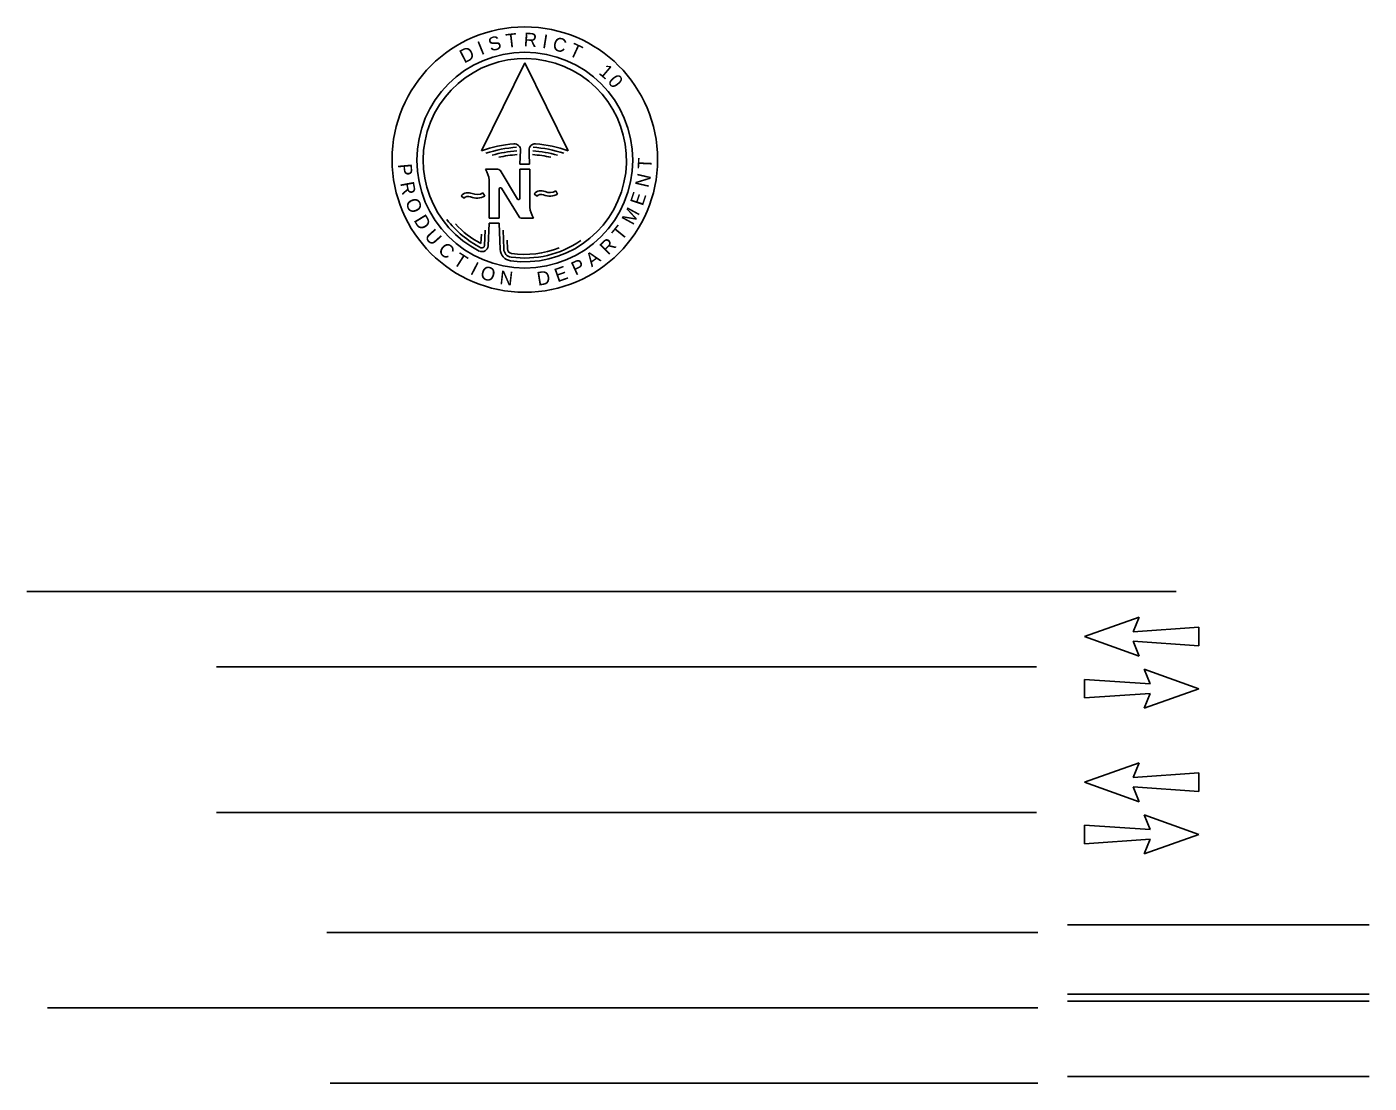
# Model space of a CAD drawing. Extents: x 396.2 to 468.4, y 232.6 to 279.1.
# Drawn here: x 423.05 to 428.91, y 248.41 to 253.02 of the extents above; entities that cross this region are included whole.
import ezdxf

# ---------------------------------------------------------------- set-up
doc = ezdxf.new("R2010")
doc.units = 0
doc.layers.add('Default', color=7, linetype='Continuous')

msp = doc.modelspace()

# ---------------------------------------------------------------- linework, layer by layer
at = {"layer": 'Default'}
for p, q in [((425.0306, 252.4821), (425.2196, 252.8661)), ((425.2196, 252.8661), (425.4086, 252.4821)), ((425.1983, 252.4232), (425.2006, 252.485)), ((425.2403, 252.4232), (425.1983, 252.4232)), ((425.2195, 252.4413), (425.2195, 252.4413)), ((425.2195, 252.4413), (425.2195, 252.4413)), ((425.2196, 252.4413), (425.2196, 252.4413)), ((425.2196, 252.4413), (425.2196, 252.4413)), ((425.2196, 252.4413), (425.2196, 252.4413)), ((425.2196, 252.4413), (425.2196, 252.4413)), ((425.0484, 252.4019), (425.1021, 252.4019)), ((425.1113, 252.3968), (425.1876, 252.271)), ((425.1975, 252.2738), (425.1975, 252.4019)), ((425.1975, 252.4019), (425.2412, 252.4019)), ((425.2412, 252.4019), (425.2412, 252.236)), ((425.0644, 252.1879), (425.0644, 252.3537)), ((425.1081, 252.3159), (425.1081, 252.1879)), ((425.1943, 252.1931), (425.1181, 252.3187)), ((425.363, 252.2929), (425.3553, 252.3068)), ((424.9416, 252.2859), (424.9533, 252.2748)), ((425.0447, 252.2843), (425.037, 252.2983)), ((425.26, 252.2946), (425.2717, 252.2835)), ((425.1081, 252.1879), (425.0644, 252.1879)), ((425.2573, 252.1879), (425.2035, 252.1879)), ((425.0469, 252.136), (425.0437, 252.0678)), ((425.0644, 252.1665), (425.0596, 252.0666)), ((425.1081, 252.1665), (425.0644, 252.1665)), ((425.1114, 252.0513), (425.1081, 252.1665)), ((425.1251, 252.1351), (425.1274, 252.0537)), ((425.0301, 252.1181), (425.0282, 252.0768)), ((425.1424, 252.0917), (425.1435, 252.0542)), ((428.0631, 250.5579), (423.0455, 250.5579)), ((427.6636, 250.3607), (427.9015, 250.4459)), ((427.9015, 250.4459), (427.8762, 250.3811)), ((427.8762, 250.3811), (428.1621, 250.4013)), ((428.1621, 250.4013), (428.162, 250.3197)), ((427.9015, 250.2753), (427.6636, 250.3607)), ((428.162, 250.3197), (427.8763, 250.3402)), ((427.8763, 250.3402), (427.9015, 250.2753)), ((427.4541, 250.2291), (423.8741, 250.2291)), ((427.9495, 250.1536), (427.924, 250.2184)), ((427.924, 250.2184), (428.1623, 250.133)), ((427.6637, 250.0924), (427.6635, 250.1736)), ((427.6635, 250.1736), (427.9495, 250.1536)), ((428.1623, 250.133), (427.9244, 250.0478)), ((427.9495, 250.1125), (427.6637, 250.0924)), ((427.9244, 250.0478), (427.9495, 250.1125)), ((427.6636, 249.7244), (427.9015, 249.8096)), ((427.9015, 249.8096), (427.8762, 249.7448)), ((427.9015, 249.639), (427.6636, 249.7244)), ((427.8762, 249.7448), (428.1621, 249.765)), ((428.1621, 249.765), (428.162, 249.6835)), ((428.162, 249.6835), (427.8763, 249.7039)), ((427.8763, 249.7039), (427.9015, 249.639)), ((427.4541, 249.5928), (423.8741, 249.5928)), ((427.9495, 249.5174), (427.924, 249.5822)), ((427.924, 249.5822), (428.1623, 249.4967)), ((427.6637, 249.4561), (427.6635, 249.5373)), ((427.6635, 249.5373), (427.9495, 249.5174)), ((428.1623, 249.4967), (427.9244, 249.4115)), ((427.9495, 249.4762), (427.6637, 249.4561)), ((427.9244, 249.4115), (427.9495, 249.4762)), ((428.9061, 249.1024), (427.5888, 249.1024)), ((427.4593, 249.0677), (424.3551, 249.0677)), ((428.9061, 248.7987), (427.5888, 248.7987)), ((427.4593, 248.739), (423.1359, 248.739)), ((428.9061, 248.7687), (427.5888, 248.7687)), ((428.9061, 248.44), (427.5888, 248.44)), ((427.4593, 248.4103), (424.3694, 248.4103))]:
    msp.add_line(p, q, dxfattribs=at)
for centre, radius in [((425.2196, 252.4439), 0.5795), ((425.2196, 252.4412), 0.4715)]:
    msp.add_circle(centre, radius, dxfattribs=at)
for centre, radius, start, end in [((425.2196, 252.4412), 0.4438, 261.93684, 243.42086), ((425.2196, 251.9499), 0.5647, 94.8642, 109.5471), ((425.2196, 251.9499), 0.5486, 93.73826, 108.099), ((425.2196, 251.9499), 0.5326, 93.73826, 105.49674), ((425.1739, 252.4859), 0.0267, 357.77965, 94.8642), ((425.2646, 252.486), 0.0267, 85.19546, 182.12377), ((437.5083, 252.94), 12.2788, 182.12377, 182.41208), ((425.2196, 251.9499), 0.5326, 74.50326, 86.26141), ((425.2196, 251.9499), 0.5486, 71.901, 86.26141), ((425.2196, 251.9499), 0.5647, 70.45266, 85.19546), ((425.2196, 251.9499), 0.5165, 93.73826, 102.75761), ((425.2196, 251.9499), 0.5165, 77.24239, 86.26141), ((424.9373, 252.3381), 0.128, 7.00127, 29.86863), ((425.1021, 252.3912), 0.0107, 31.24731, 90), ((424.9722, 252.257), 0.0421, 65.79325, 136.76575), ((425.1135, 252.3159), 0.00535, 31.24622, 180), ((425.2907, 252.2657), 0.0421, 65.79325, 136.76575), ((425.3288, 252.3538), 0.0539, 247.19582, 299.48448), ((424.9722, 252.257), 0.026, 65.79325, 136.76575), ((425.0102, 252.3452), 0.07, 247.19582, 299.48448), ((425.0104, 252.3451), 0.0539, 247.19582, 299.48448), ((425.1921, 252.2738), 0.00535, 211.24622, 0), ((425.2907, 252.2657), 0.026, 65.79325, 136.76575), ((425.3286, 252.3539), 0.07, 247.19582, 299.48448), ((425.2196, 252.4412), 0.4277, 217.27521, 243.42077), ((425.2035, 252.1986), 0.0107, 211.24731, 270), ((425.3683, 252.2516), 0.128, 187.00127, 209.86863), ((425.2196, 252.4412), 0.4117, 222.56637, 242.2942), ((425.033, 252.0683), 0.0267, 243.42086, 356.26509), ((425.033, 252.0683), 0.0107, 243.42077, 357.31292), ((425.2196, 252.4412), 0.4277, 261.94105, 304.81679), ((425.1648, 252.0548), 0.0535, 183.80636, 261.93684), ((425.1649, 252.0548), 0.0374, 181.63859, 261.94105), ((425.1648, 252.0548), 0.0214, 181.63732, 261.93938), ((425.2196, 252.4412), 0.4117, 261.93938, 291.31687)]:
    msp.add_arc(centre, radius, start, end, dxfattribs=at)

# ---------------------------------------------------------------- texts
for s, rotation, p in [('I', 22.18433, (425.0287, 252.8991)), ('S', 16.96646, (425.0708, 252.9146)), ('T', 6.5307, (425.1401, 252.9316)), ('R', 356.09495, (425.2133, 252.9391)), ('I', 350.87707, (425.2928, 252.932)), ('C', 345.6592, (425.3366, 252.9234)), ('T', 335.22345, (425.4078, 252.9006)), ('D', 27.40221, (424.9548, 252.8626)), ('1', 319.56982, (425.5389, 252.8202)), ('0', 309.13407, (425.5786, 252.7847)), ('P', 275.23459, (424.6655, 252.4235)), ('T', 87.40778, (425.7719, 252.4012)), ('N', 76.98874, (425.7586, 252.318)), ('R', 280.45247, (424.6755, 252.3418)), ('E', 71.77087, (425.7347, 252.2382)), ('O', 290.88822, (424.6965, 252.2617)), ('D', 301.32397, (424.7326, 252.1793)), ('M', 61.33512, (425.6919, 252.1537)), ('U', 311.75972, (424.7784, 252.1067)), ('T', 50.89936, (425.6419, 252.0858)), ('C', 316.9776, (424.8364, 252.0443)), ('R', 45.68149, (425.5833, 252.024)), ('T', 327.41335, (424.9024, 251.9896)), ('P', 24.80999, (425.4402, 251.9361)), ('A', 35.24574, (425.5116, 251.9724)), ('I', 332.63123, (424.9771, 251.946)), ('O', 343.06698, (425.0207, 251.9257)), ('N', 353.50273, (425.107, 251.8996)), ('D', 9.15636, (425.2775, 251.8925)), ('E', 19.59211, (425.3622, 251.907))]:
    msp.add_text(s, height=0.0601, rotation=rotation, dxfattribs=at).set_placement(p)

doc.saveas('drawing.dxf')
